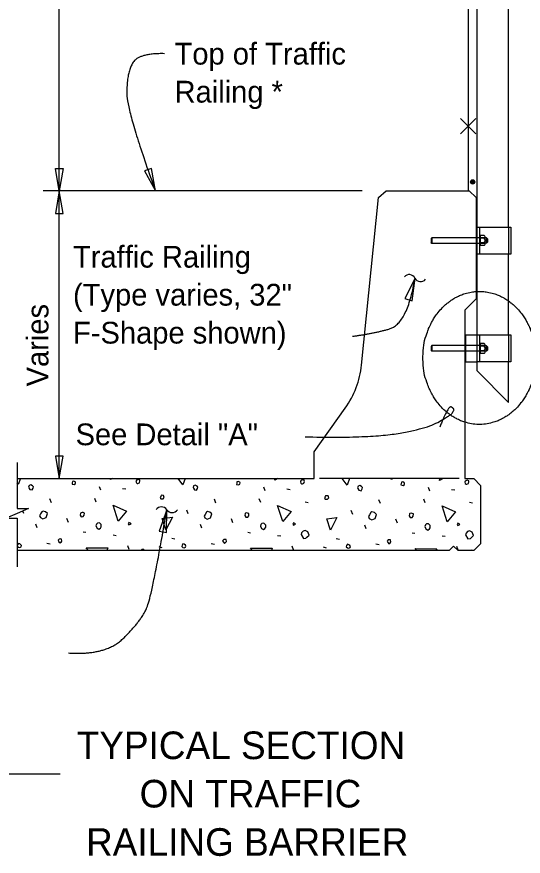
# Model space of a CAD drawing. Extents: x 0 to 41, y -96 to 25.
# Drawn here: x 29.01 to 33.7, y -85.03 to -77.25 of the extents above; entities that cross this region are included whole.
import ezdxf

# ---------------------------------------------------------------- set-up
doc = ezdxf.new("R2010")
doc.units = 0
for name, color, linetype in [('Dimension', 7, 'Continuous'), ('Miscellaneous', 7, 'Continuous'), ('SteelMisc', 7, 'Continuous'), ('SteelMisc_h', 7, 'Continuous'), ('SupstrConc', 7, 'Continuous'), ('SupstrConc_h', 7, 'Continuous'), ('TextStructures', 7, 'Continuous')]:
    doc.layers.add(name, color=color, linetype=linetype)

msp = doc.modelspace()

# ---------------------------------------------------------------- linework, layer by layer
at = {"layer": 'Dimension'}
for p, q in [((29.4061, -81.5297), (29.4061, -72.863)), ((32.214, -78.863), (29.2561, -78.863)), ((23.6151, -84.2642), (29.4153, -84.2642))]:
    msp.add_line(p, q, dxfattribs=at)
for points in [[(29.4061, -78.863), (29.3708, -78.6548), (29.4413, -78.6548)], [(30.2977, -78.863), (30.2616, -78.6549), (30.1951, -78.6784)], [(29.4061, -78.863), (29.3708, -79.0713), (29.4413, -79.0713)], [(32.7026, -79.6709), (32.6085, -79.86), (32.676, -79.8805)], [(29.4061, -81.5297), (29.4413, -81.3214), (29.3708, -81.3214)], [(30.403, -81.8172), (30.3312, -82.0159), (30.4006, -82.0284)]]:
    msp.add_lwpolyline(points, close=True, dxfattribs=at)
msp.add_lwpolyline([(29.0176, -81.3797), (29.0176, -81.8068), (29.1209, -81.8068), (29.0176, -81.8518), (28.9142, -81.8968), (29.0176, -81.8968), (29.0176, -82.3464)], dxfattribs=at)
for centre, start, end in [((32.6489, -79.6982), 27.32823, 139.05545), ((32.7548, -79.6434), 207.32823, 319.05545), ((30.3527, -81.8505), 33.91896, 145.64618), ((30.4517, -81.784), 213.91896, 325.64618)]:
    msp.add_arc(centre, 0.0596, start, end, dxfattribs=at)
for points, degree in [([(30.3802, -77.5916), (30.1383, -77.5857), (30.0322, -77.7746), (30.0322, -78.1289), (30.2976, -78.863)], 2), ([(32.1233, -80.2096), (32.2959, -80.1899), (32.6322, -80.0946), (32.7026, -79.671)], 2), ([(33.2986, -81.0268), (33.3336, -81.0268), (33.3683, -81.0226), (33.4362, -81.0065), (33.4694, -80.9945), (33.5172, -80.9709), (33.5328, -80.9621), (33.5556, -80.9476), (33.5631, -80.9425), (33.5779, -80.9319), (33.5851, -80.9264), (33.6208, -80.898), (33.6471, -80.8721), (33.695, -80.815), (33.7165, -80.7838), (33.7399, -80.7419), (33.7444, -80.7334), (33.7531, -80.7161), (33.7573, -80.7073), (33.7692, -80.6806), (33.7764, -80.6625), (33.8084, -80.5701), (33.8217, -80.491), (33.8217, -80.3307), (33.8084, -80.2516), (33.7764, -80.1592), (33.7692, -80.1411), (33.7573, -80.1145), (33.7531, -80.1057), (33.7444, -80.0884), (33.7399, -80.0799), (33.7165, -80.038), (33.695, -80.0067), (33.6471, -79.9496), (33.6208, -79.9237), (33.5851, -79.8953), (33.5779, -79.8898), (33.5631, -79.8793), (33.5556, -79.8742), (33.5328, -79.8596), (33.5172, -79.8508), (33.4694, -79.8272), (33.4362, -79.8152), (33.3683, -79.7991), (33.3336, -79.795), (33.2636, -79.795), (33.2289, -79.7991), (33.1609, -79.8152), (33.1278, -79.8272), (33.08, -79.8508), (33.0644, -79.8596), (33.0416, -79.8742), (33.0341, -79.8793), (33.0193, -79.8898), (33.0121, -79.8953), (32.9764, -79.9237), (32.9501, -79.9496), (32.9022, -80.0067), (32.8807, -80.038), (32.8573, -80.0799), (32.8527, -80.0884), (32.8441, -80.1057), (32.8399, -80.1145), (32.828, -80.1411), (32.8208, -80.1592), (32.7887, -80.2516), (32.7755, -80.3307), (32.7755, -80.491), (32.7887, -80.5701), (32.8208, -80.6625), (32.828, -80.6806), (32.8399, -80.7073), (32.8441, -80.7161), (32.8527, -80.7334), (32.8573, -80.7419), (32.8807, -80.7838), (32.9022, -80.815), (32.9501, -80.8721), (32.9764, -80.898), (33.0121, -80.9264), (33.0193, -80.9319), (33.0341, -80.9425), (33.0416, -80.9476), (33.0644, -80.9621), (33.08, -80.9709), (33.1278, -80.9945), (33.1609, -81.0065), (33.2289, -81.0226), (33.2636, -81.0268), (33.2986, -81.0268)], 3), ([(31.6835, -81.1426), (32.2811, -81.155), (32.8178, -81.0651), (33.0428, -80.9329), (33.0535, -80.9109), (33.0697, -80.885), (33.0105, -80.8473), (32.9324, -81.0515)], 2), ([(29.4916, -83.1449), (29.8372, -83.1681), (30.1609, -82.8529), (30.2688, -82.6106), (30.4029, -81.8169)], 2)]:
    msp.add_open_spline(points, degree=degree, dxfattribs=at)
at = {"layer": 'Miscellaneous'}
for p, q in [((33.2653, -78.1924), (33.1239, -78.3336)), ((33.1239, -78.1924), (33.2653, -78.3336)), ((33.2676, -79.1982), (33.278, -79.1982)), ((33.2712, -79.1982), (33.2712, -79.4482)), ((33.2745, -79.1982), (33.2745, -79.4482)), ((33.3586, -79.312), (33.3586, -79.3328)), ((33.3683, -79.312), (33.3683, -79.3328)), ((33.278, -79.4482), (33.2676, -79.4482)), ((33.1634, -80.1982), (33.1738, -80.1982)), ((33.167, -80.1982), (33.167, -80.4482)), ((33.1703, -80.1982), (33.1703, -80.4482)), ((33.3586, -80.312), (33.3586, -80.3328)), ((33.3683, -80.312), (33.3683, -80.3328)), ((33.1738, -80.4482), (33.1634, -80.4482)), ((30.9661, -81.5297), (30.9674, -81.53)), ((32.4722, -81.5297), (32.4912, -81.5335)), ((29.7919, -81.6378), (29.7795, -81.6042)), ((29.9916, -81.6219), (30.0234, -81.6254)), ((31.3157, -81.6413), (31.3033, -81.6078)), ((31.5154, -81.6254), (31.5473, -81.629)), ((32.8395, -81.6449), (32.8271, -81.6113)), ((33.0392, -81.629), (33.0711, -81.6325)), ((29.334, -81.7527), (29.3199, -81.7174)), ((29.7494, -81.7474), (29.7353, -81.712)), ((30.8578, -81.7562), (30.8437, -81.7209)), ((31.2732, -81.7509), (31.2591, -81.7156)), ((31.6834, -81.7439), (31.7117, -81.7509)), ((32.3816, -81.7598), (32.3675, -81.7244)), ((32.7971, -81.7545), (32.7829, -81.7191)), ((33.2072, -81.7474), (33.2355, -81.7545)), ((29.0777, -81.8535), (29.0682, -81.8298)), ((30.6015, -81.857), (30.5874, -81.8217)), ((32.1253, -81.8605), (32.1112, -81.8252)), ((29.4913, -81.9348), (29.4772, -81.8994)), ((31.0152, -81.9383), (31.001, -81.903)), ((32.539, -81.9419), (32.5248, -81.9065)), ((29.2032, -81.9861), (29.1908, -81.9525)), ((30.727, -81.9896), (30.7146, -81.956)), ((32.2508, -81.9931), (32.2384, -81.9595)), ((29.6292, -82.0232), (29.654, -82.0267)), ((29.905, -82.0515), (29.935, -82.0568)), ((31.153, -82.0267), (31.1778, -82.0302)), ((31.4288, -82.055), (31.4589, -82.0603)), ((32.6769, -82.0302), (32.7016, -82.0338)), ((32.9526, -82.0585), (32.9827, -82.0638)), ((29.2916, -82.1275), (29.3216, -82.1328)), ((30.4495, -82.0797), (30.4778, -82.0868)), ((30.8154, -82.131), (30.8454, -82.1363)), ((31.9733, -82.0833), (32.0016, -82.0904)), ((32.3392, -82.1345), (32.3693, -82.1398)), ((30.0535, -82.1858), (30.0411, -82.1522)), ((30.3275, -82.1593), (30.3558, -82.1664)), ((31.5773, -82.1893), (31.5649, -82.1558)), ((31.8513, -82.1628), (31.8796, -82.1699)), ((33.1011, -82.1929), (33.0887, -82.1593))]:
    msp.add_line(p, q, dxfattribs=at)
for points in [[(33.1947, -72.863), (33.1947, -78.863)], [(29.0264, -81.583), (29.0176, -81.5714)], [(29.0463, -81.5297), (29.0264, -81.583)], [(29.1254, -81.6148), (29.1343, -81.6307), (29.1555, -81.6343), (29.1643, -81.6184), (29.1678, -81.6042), (29.159, -81.5954), (29.1431, -81.5865), (29.1272, -81.5918), (29.1219, -81.6078), (29.1254, -81.6148)], [(29.5249, -81.5795), (29.5444, -81.5848), (29.5567, -81.5759), (29.5585, -81.5636), (29.555, -81.56), (29.5408, -81.553), (29.5285, -81.5547), (29.5267, -81.5671), (29.5249, -81.5795)], [(29.8802, -81.5388), (29.8831, -81.5297)], [(29.9005, -81.5297), (29.8802, -81.5388)], [(30.1277, -81.5742), (30.1348, -81.5742), (30.1489, -81.5671), (30.1543, -81.5512), (30.1525, -81.5423), (30.1383, -81.5353), (30.1207, -81.5459), (30.1171, -81.5565), (30.1207, -81.5671), (30.1277, -81.5742)], [(30.5502, -81.5865), (30.507, -81.5297)], [(30.5715, -81.5297), (30.5502, -81.5865)], [(30.6492, -81.6184), (30.6581, -81.6343), (30.6793, -81.6378), (30.6881, -81.6219), (30.6917, -81.6078), (30.6828, -81.5989), (30.6669, -81.5901), (30.651, -81.5954), (30.6457, -81.6113), (30.6492, -81.6184)], [(31.0487, -81.583), (31.0682, -81.5883), (31.0806, -81.5795), (31.0823, -81.5671), (31.0788, -81.5636), (31.0647, -81.5565), (31.0523, -81.5583), (31.0505, -81.5706), (31.0487, -81.583)], [(31.4041, -81.5423), (31.408, -81.5297)], [(31.4322, -81.5297), (31.4041, -81.5423)], [(31.6516, -81.5777), (31.6586, -81.5777), (31.6728, -81.5706), (31.6781, -81.5547), (31.6763, -81.5459), (31.6622, -81.5388), (31.6445, -81.5494), (31.6409, -81.56), (31.6445, -81.5706), (31.6516, -81.5777)], [(32.074, -81.5901), (32.0282, -81.5297)], [(32.0966, -81.5297), (32.074, -81.5901)], [(32.173, -81.6219), (32.1819, -81.6378), (32.2031, -81.6413), (32.2119, -81.6254), (32.2155, -81.6113), (32.2066, -81.6024), (32.1907, -81.5936), (32.1748, -81.5989), (32.1695, -81.6148), (32.173, -81.6219)], [(32.5726, -81.5865), (32.592, -81.5918), (32.6044, -81.583), (32.6061, -81.5706), (32.6026, -81.5671), (32.5885, -81.56), (32.5761, -81.5618), (32.5743, -81.5742), (32.5726, -81.5865)], [(32.9279, -81.5459), (32.9329, -81.5297)], [(32.9639, -81.5297), (32.9279, -81.5459)], [(33.1754, -81.5812), (33.1824, -81.5812), (33.1966, -81.5742), (33.2019, -81.5583), (33.2001, -81.5494), (33.186, -81.5423), (33.1683, -81.553), (33.1648, -81.5636), (33.1683, -81.5742), (33.1754, -81.5812)], [(30.3469, -81.7156), (30.3682, -81.7156), (30.3788, -81.705), (30.3735, -81.6855), (30.3505, -81.6838), (30.3469, -81.6944), (30.3416, -81.7032), (30.3469, -81.7156), (30.3434, -81.712)], [(31.8708, -81.7191), (31.892, -81.7191), (31.9026, -81.7085), (31.8973, -81.6891), (31.8743, -81.6873), (31.8708, -81.6979), (31.8654, -81.7067), (31.8708, -81.7191), (31.8672, -81.7156)], [(29.2315, -81.8906), (29.2545, -81.903), (29.2845, -81.8906), (29.2969, -81.8535), (29.2792, -81.8358), (29.2562, -81.8305), (29.2456, -81.8376), (29.2332, -81.857), (29.2244, -81.8729), (29.2315, -81.8906)], [(29.9527, -81.9224), (29.905, -81.7757), (30.0305, -81.8305), (29.9527, -81.9224)], [(31.4765, -81.9259), (31.4288, -81.7792), (31.5543, -81.834), (31.4765, -81.9259)], [(33.0004, -81.9295), (32.9526, -81.7828), (33.0781, -81.8376), (33.0004, -81.9295)], [(29.6009, -81.8676), (29.6098, -81.8835), (29.6292, -81.8818), (29.6381, -81.8694), (29.6398, -81.8499), (29.6275, -81.8446), (29.6186, -81.8429), (29.608, -81.8464), (29.6045, -81.8499), (29.6009, -81.8676)], [(30.3947, -82.0037), (30.3611, -81.8994), (30.4548, -81.8871), (30.3947, -82.0037)], [(30.7553, -81.8941), (30.7783, -81.9065), (30.8083, -81.8941), (30.8207, -81.857), (30.803, -81.8393), (30.78, -81.834), (30.7694, -81.8411), (30.7571, -81.8605), (30.7482, -81.8765), (30.7553, -81.8941)], [(31.1248, -81.8711), (31.1336, -81.8871), (31.153, -81.8853), (31.1619, -81.8729), (31.1636, -81.8535), (31.1513, -81.8482), (31.1424, -81.8464), (31.1318, -81.8499), (31.1283, -81.8535), (31.1248, -81.8711)], [(31.9185, -82.0073), (31.8849, -81.903), (31.9786, -81.8906), (31.9185, -82.0073)], [(32.2791, -81.8977), (32.3021, -81.91), (32.3321, -81.8977), (32.3445, -81.8605), (32.3268, -81.8429), (32.3039, -81.8376), (32.2932, -81.8446), (32.2809, -81.8641), (32.272, -81.88), (32.2791, -81.8977)], [(32.6486, -81.8747), (32.6574, -81.8906), (32.6769, -81.8888), (32.6857, -81.8765), (32.6875, -81.857), (32.6751, -81.8517), (32.6662, -81.8499), (32.6556, -81.8535), (32.6521, -81.857), (32.6486, -81.8747)], [(29.7459, -81.9666), (29.7565, -81.9878), (29.7742, -81.9984), (29.7883, -81.9878), (29.7954, -81.9772), (29.7954, -81.956), (29.7795, -81.9401), (29.76, -81.9419), (29.7512, -81.9507), (29.7459, -81.9666)], [(30.0517, -81.9578), (30.0712, -81.9489), (30.0641, -81.9419), (30.0517, -81.9366), (30.0464, -81.9489), (30.0517, -81.9578)], [(31.2697, -81.9701), (31.2803, -81.9914), (31.298, -82.002), (31.3121, -81.9914), (31.3192, -81.9807), (31.3192, -81.9595), (31.3033, -81.9436), (31.2839, -81.9454), (31.275, -81.9542), (31.2697, -81.9701)], [(31.5755, -81.9613), (31.595, -81.9525), (31.5879, -81.9454), (31.5755, -81.9401), (31.5702, -81.9525), (31.5755, -81.9613)], [(32.7935, -81.9737), (32.8041, -81.9949), (32.8218, -82.0055), (32.836, -81.9949), (32.843, -81.9843), (32.843, -81.9631), (32.8271, -81.9472), (32.8077, -81.9489), (32.7988, -81.9578), (32.7935, -81.9737)], [(33.0994, -81.9648), (33.1188, -81.956), (33.1117, -81.9489), (33.0994, -81.9436), (33.094, -81.956), (33.0994, -81.9648)], [(31.6462, -82.0462), (31.6692, -82.0833), (31.6922, -82.0815), (31.701, -82.0727), (31.7205, -82.0532), (31.7081, -82.0232), (31.6834, -82.009), (31.6657, -82.0161), (31.6516, -82.0302), (31.6462, -82.0462)], [(33.1701, -82.0497), (33.193, -82.0868), (33.216, -82.085), (33.2249, -82.0762), (33.2443, -82.0568), (33.2319, -82.0267), (33.2072, -82.0126), (33.1895, -82.0196), (33.1754, -82.0338), (33.1701, -82.0497)], [(29.0282, -82.1646), (29.0406, -82.1664), (29.0529, -82.1611), (29.0565, -82.1505), (29.0512, -82.1416), (29.0406, -82.1345), (29.0282, -82.1292), (29.0211, -82.1434), (29.0176, -82.154)], [(29.403, -82.1151), (29.4136, -82.1257), (29.4242, -82.1186), (29.4312, -82.108), (29.4277, -82.0904), (29.4189, -82.0886), (29.4065, -82.0904), (29.3959, -82.101), (29.403, -82.1151)], [(30.552, -82.1681), (30.5644, -82.1699), (30.5767, -82.1646), (30.5803, -82.154), (30.575, -82.1452), (30.5644, -82.1381), (30.552, -82.1328), (30.5449, -82.1469), (30.5414, -82.1575), (30.552, -82.1681)], [(30.9268, -82.1186), (30.9374, -82.1292), (30.948, -82.1222), (30.955, -82.1116), (30.9515, -82.0939), (30.9427, -82.0921), (30.9303, -82.0939), (30.9197, -82.1045), (30.9268, -82.1186)], [(32.0758, -82.1717), (32.0882, -82.1734), (32.1006, -82.1681), (32.1041, -82.1575), (32.0988, -82.1487), (32.0882, -82.1416), (32.0758, -82.1363), (32.0687, -82.1505), (32.0652, -82.1611), (32.0758, -82.1717)], [(32.4506, -82.1222), (32.4612, -82.1328), (32.4718, -82.1257), (32.4789, -82.1151), (32.4753, -82.0974), (32.4665, -82.0957), (32.4541, -82.0974), (32.4435, -82.108), (32.4506, -82.1222)], [(29.0176, -82.154), (29.0282, -82.1646)], [(29.6759, -82.1964), (29.6557, -82.1699), (29.8555, -82.1717), (29.8462, -82.1964)], [(30.1932, -82.1964), (30.1913, -82.1873), (30.1825, -82.1855), (30.1701, -82.1873), (30.161, -82.1964)], [(31.197, -82.1964), (31.1796, -82.1734), (31.3793, -82.1752), (31.3714, -82.1964)], [(32.7181, -82.1964), (32.7034, -82.177), (32.9031, -82.1787), (32.8965, -82.1964)], [(33.2394, -82.1964), (33.239, -82.1944), (33.2301, -82.1926), (33.2178, -82.1944), (33.2157, -82.1964)]]:
    msp.add_lwpolyline(points, dxfattribs=at)
at = {"layer": 'SteelMisc'}
for p, q in [((33.1947, -72.863), (33.1947, -78.863)), ((33.278, -79.1982), (33.278, -72.863)), ((33.5697, -79.1982), (33.5697, -72.863)), ((33.278, -79.4482), (33.278, -79.1982)), ((33.278, -79.1982), (33.5905, -79.1982)), ((33.2988, -79.1982), (33.2988, -79.4482)), ((33.5905, -79.1982), (33.5905, -79.4482)), ((33.3059, -79.2735), (33.2988, -79.2735)), ((33.3059, -79.2735), (33.3059, -79.3729)), ((33.3436, -79.2778), (33.3059, -79.2778)), ((33.3059, -79.3685), (33.3059, -79.2778)), ((33.3438, -79.3005), (33.3059, -79.3005)), ((33.3523, -79.3572), (33.3523, -79.2891)), ((33.3635, -79.2974), (33.3523, -79.2974)), ((33.3635, -79.2974), (33.3635, -79.3489)), ((33.3732, -79.3071), (33.3635, -79.2974)), ((33.3732, -79.3376), (33.3635, -79.3489)), ((33.3732, -79.3071), (33.3732, -79.3376)), ((33.3059, -79.3729), (33.2988, -79.3729)), ((33.3438, -79.3458), (33.3059, -79.3458)), ((33.3436, -79.3685), (33.3059, -79.3685)), ((33.3635, -79.3489), (33.3523, -79.3489)), ((33.278, -80.5315), (33.278, -79.4482)), ((33.5905, -79.4482), (33.278, -79.4482)), ((33.5697, -80.1982), (33.5697, -79.4482)), ((33.1738, -80.4482), (33.1738, -80.1982)), ((33.1738, -80.1982), (33.278, -80.1982)), ((33.278, -80.1982), (33.5905, -80.1982)), ((33.2988, -80.1982), (33.2988, -80.4482)), ((33.3059, -80.2735), (33.2988, -80.2735)), ((33.3059, -80.2735), (33.3059, -80.3729)), ((33.5905, -80.1982), (33.5905, -80.4482)), ((33.3436, -80.2778), (33.3059, -80.2778)), ((33.3059, -80.3685), (33.3059, -80.2778)), ((33.3438, -80.3005), (33.3059, -80.3005)), ((33.3438, -80.3458), (33.3059, -80.3458)), ((33.3523, -80.3572), (33.3523, -80.2891)), ((33.3635, -80.2974), (33.3523, -80.2974)), ((33.3635, -80.3489), (33.3523, -80.3489)), ((33.3635, -80.2974), (33.3635, -80.3489)), ((33.3732, -80.3071), (33.3635, -80.2974)), ((33.3732, -80.3376), (33.3635, -80.3489)), ((33.3732, -80.3071), (33.3732, -80.3376)), ((33.3059, -80.3729), (33.2988, -80.3729)), ((33.3436, -80.3685), (33.3059, -80.3685)), ((33.1738, -80.4482), (33.278, -80.4482)), ((33.5905, -80.4482), (33.278, -80.4482)), ((33.5697, -80.8232), (33.5697, -80.4482))]:
    msp.add_line(p, q, dxfattribs=at)
msp.add_lwpolyline([(33.278, -80.5315), (33.5697, -80.8232)], dxfattribs=at)
for radius in [0.0197, 0.0172, 0.0147, 0.0122, 0.00975, 0.00725, 0.00475, 0.00225]:
    msp.add_circle((33.2363, -78.7797), radius, dxfattribs=at)
for centre, radius, start, end in [((33.3405, -79.2892), 0.0118, 286.59863, 74.70054), ((33.3176, -79.3232), 0.0347, 319.20147, 40.79853), ((33.3405, -79.3572), 0.0118, 285.15064, 73.50417), ((33.3405, -80.2892), 0.0118, 286.59863, 74.70054), ((33.3405, -80.3572), 0.0118, 285.15064, 73.50417), ((33.3176, -80.3232), 0.0347, 319.20147, 40.79853)]:
    msp.add_arc(centre, radius, start, end, dxfattribs=at)
at = {"layer": 'SteelMisc_h'}
for p, q in [((33.5697, -79.1982), (33.5697, -79.4482)), ((32.859, -79.2971), (32.8509, -79.3054)), ((32.8509, -79.3054), (32.8509, -79.341)), ((32.859, -79.3492), (32.8509, -79.341)), ((33.3523, -79.2971), (32.859, -79.2971)), ((32.859, -79.2971), (32.859, -79.3492)), ((33.3523, -79.3492), (32.859, -79.3492)), ((33.5697, -80.1982), (33.5697, -80.4482)), ((32.859, -80.2971), (32.8509, -80.3054)), ((32.8509, -80.3054), (32.8509, -80.341)), ((32.859, -80.3492), (32.8509, -80.341)), ((33.3523, -80.2971), (32.859, -80.2971)), ((32.859, -80.2971), (32.859, -80.3492)), ((33.3523, -80.3492), (32.859, -80.3492))]:
    msp.add_line(p, q, dxfattribs=at)
at = {"layer": 'SupstrConc'}
for p, q in [((32.3654, -78.9253), (32.4342, -78.8631)), ((32.4343, -78.863), (33.2051, -78.863)), ((33.2051, -78.8631), (33.2676, -78.9256)), ((32.2067, -80.4766), (32.3654, -78.9253)), ((33.2676, -78.9256), (33.2676, -79.8631)), ((33.2676, -79.8631), (33.1634, -79.9672)), ((33.1634, -79.9672), (33.1634, -81.5297)), ((31.7676, -81.2797), (32.0559, -80.8761)), ((31.7676, -81.5297), (31.7676, -81.2797)), ((29.0176, -81.5297), (31.7676, -81.5297)), ((33.1634, -81.5297), (33.2467, -81.5297)), ((33.2467, -81.5297), (33.3092, -81.5922)), ((33.3092, -81.5922), (33.3092, -82.1339)), ((33.3092, -82.1339), (33.2467, -82.1964)), ((33.0175, -82.1964), (29.0176, -82.1964)), ((33.0175, -82.1964), (33.0592, -82.1547)), ((33.0592, -82.1547), (33.1009, -82.1964)), ((33.2467, -82.1964), (33.1009, -82.1964))]:
    msp.add_line(p, q, dxfattribs=at)
msp.add_arc((31.3778, -80.392), 0.8333, 324.46232, 354.16034, dxfattribs=at)
at = {"layer": 'SupstrConc_h'}
msp.add_line((33.1124, -81.5297), (31.8186, -81.5297), dxfattribs=at)

# ---------------------------------------------------------------- texts
at = {"layer": 'Dimension'}
for s, height, p in [('Top of Traffic ', 0.2016, (30.4747, -77.6926)), ('Railing *', 0.2016, (30.4747, -78.0446)), ('Traffic Railing ', 0.2016, (29.5341, -79.5739)), ('(Type varies, 32" ', 0.2016, (29.5341, -79.9259)), ('F-Shape shown)', 0.2016, (29.5341, -80.2779)), ('TYPICAL SECTION', 0.256001, (29.5683, -84.1287)), ('ON TRAFFIC', 0.256, (30.1511, -84.5767)), ('RAILING BARRIER', 0.256001, (29.6545, -85.0247))]:
    msp.add_text(s, height=height, dxfattribs=at).set_placement(p)
at = {"layer": 'TextStructures'}
msp.add_text('Varies', height=0.2016, rotation=90, dxfattribs=at).set_placement((29.3061, -80.6749))
msp.add_text('See Detail "A"', height=0.2016, dxfattribs=at).set_placement((29.5575, -81.2199))

doc.saveas('drawing.dxf')
